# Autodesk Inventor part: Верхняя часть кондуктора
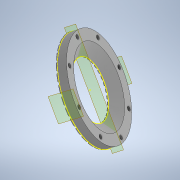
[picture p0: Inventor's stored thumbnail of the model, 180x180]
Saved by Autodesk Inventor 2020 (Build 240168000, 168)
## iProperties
Created: 2024-03
Part Number: Верхняя часть кондуктора
Material: Типовые
Document SubType Name: Modeling
Designer: User
Density: 1 g/cm^3
Appearance: Светло-серый
Author: User
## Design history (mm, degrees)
sketch "Эскиз1"
  geometry: C1 r 16 at (0, 0); C2 r 46 at (0, 0); 1 further point
  constraints: 2 centre point, 2 coincident
  dimensions: "d0" = 32 diameter of C1; "d1" = 92 diameter of C2
extrude "Выдавливание1" new body sketch "Эскиз1" distance "d2" = 2; taper "d3" = 0 deg
sketch "Эскиз2"
  geometry: C1 r 26 at (0, 0); C2 r 36 at (0, 0); C3 r 46 at (0, 0); 1 further point
  constraints: 3 centre point, 3 coincident
  dimensions: "d4" = 52 diameter of C1; "d14" = 92 diameter of C3
extrude "Выдавливание2" join sketch "Эскиз2" distance "d5" = 6.05; taper "d6" = 0 deg
sketch "Эскиз3"
  geometry: L1 (0, 46)-(0, 26); 3 further points
  constraints: 2 end point, 2 vertical alignment, 1 vertical, 2 other
node "РабПлоскость1"
sketch "Эскиз5"
  geometry: L1 (0, -46)-(0, 46) reference; L2 (0, 0)-(-1.5, 0); C1 r 1.5 at (-1.5, 0); 1 further point
  constraints: 2 end point, 1 centre point, 1 coincident, 1 horizontal, 1 midpoint
  dimensions: "d15" = 1.5 distance of L2.start L2.end; "d16" = 3 diameter of C1
extrude "Выдавливание4" cut sketch "Эскиз5" distance "d17" = 40; taper "d18" = 0 deg
sketch "Эскиз6"
  geometry: C1 r 16 at (0, 0); C2 r 46 at (0, 0); 1 further point
  constraints: 2 centre point, 2 coincident
extrude "Выдавливание5" join sketch "Эскиз6" distance "d22" = 8; taper "d23" = 0 deg
sketch "Эскиз7"
  geometry: L1 (-8.974, 45.116)-(-5.072, 25.5) reference; C1 r 1.5 at (-4.099, 41.618); A1 r 46 centre (0, 0) between (0, 46) and (-8.974, 45.116) reference; 1 further point
  constraints: 1 centre point
  dimensions: "d26" = 3 diameter of C1
extrude "Выдавливание6" cut sketch "Эскиз7" distance "d27" = 40; taper "d28" = 0 deg
sketch "Эскиз8"
  geometry: C1 r 26 at (0, 0); C2 r 46 at (0, 0); C3 r 1.5 at (-4.099, 41.618) reference; C4 r 1.5 at (-4.099, 41.618); 1 further point
  constraints: 3 centre point, 3 coincident
  dimensions: "d29" = 3 diameter of C4
extrude "Выдавливание7" join sketch "Эскиз8" distance "d30" = 8; taper "d31" = 0 deg
pattern_circular "Круговой массив3" dims angle "d33" = 360 deg
sketch "Эскиз9"
  geometry: C1 r 1.5 at (0, 0) reference; C2 r 1.5 at (0, 0); 1 further point
  constraints: 1 centre point, 1 coincident
  dimensions: "d35" = 3 diameter of C2
extrude "Выдавливание8" cut sketch "Эскиз9" distance "d36" = 20; taper "d37" = 0 deg
sketch "Эскиз10"
  geometry: C1 r 1.5 at (0, 0) reference; C2 r 1.5 at (0, 0); C3 r 1.5 at (-15.088, -28.228) reference; C4 r 1.5 at (-15.088, -28.228); C5 r 1.5 at (-45.718, -37.519) reference; C6 r 1.5 at (-45.718, -37.519); C7 r 1.5 at (-73.946, -22.431) reference; C8 r 1.5 at (-73.946, -22.431); C9 r 1.5 at (-83.237, 8.198) reference; C10 r 1.5 at (-83.237, 8.198); C11 r 1.5 at (-68.149, 36.426) reference; C12 r 1.5 at (-68.149, 36.426); 1 further point
  constraints: 6 centre point, 6 coincident
  dimensions: "d38" = 3 diameter of C2; "d39" = 3 diameter of C4; "d40" = 3 diameter of C6; "d41" = 3 diameter of C8; "d42" = 3 diameter of C10; "d43" = 3 diameter of C12
extrude "Выдавливание9" cut sketch "Эскиз10" distance "d44" = 20; taper "d45" = 0 deg
sketch "Эскиз11"
  geometry: L1 (60.933, 75.393)-(-60.762, 75.393); L2 (-60.762, 75.393)-(-60.762, -75.327); L3 (-60.762, -75.327)-(60.933, -75.327); L4 (60.933, -75.327)-(60.933, 75.393); 1 further point
  constraints: 8 end point, 2 parallel, 1 horizontal, 1 perpendicular
extrude "Выдавливание10" cut sketch "Эскиз11" distance "d46" = 15; taper "d47" = 0 deg
sketch "Эскиз12"
  geometry: C1 r 1.5 at (-26.53, -32.327) reference; C2 r 2 at (-26.53, -32.327); C3 r 1.5 at (-41.618, -4.099) reference; C4 r 2 at (-41.618, -4.099); C5 r 1.5 at (-32.327, 26.53) reference; C6 r 2 at (-32.327, 26.53); C7 r 1.5 at (-4.099, 41.618) reference; C8 r 2 at (-4.099, 41.618); C9 r 1.5 at (26.53, 32.327) reference; C10 r 2 at (26.53, 32.327); C11 r 1.5 at (41.618, 4.099) reference; C12 r 2 at (41.618, 4.099); C13 r 1.5 at (32.327, -26.53) reference; C14 r 2 at (32.327, -26.53); C15 r 1.5 at (4.099, -41.618) reference; C16 r 2 at (4.099, -41.618); 1 further point
  constraints: 8 centre point, 8 coincident
  dimensions: "d48" = 4 diameter of C2; "d49" = 4 diameter of C4; "d50" = 4 diameter of C6; "d51" = 4 diameter of C8; "d52" = 4 diameter of C10; "d53" = 4 diameter of C12; "d54" = 4 diameter of C14; "d55" = 4 diameter of C16
extrude "Выдавливание11" cut sketch "Эскиз12" distance "d56" = 15; taper "d57" = 0 deg
node "РабПлоскость3"
  node "РабПлоскость2"
sketch "Эскиз13"
  geometry: L1 (8, -26)-(0, -26) reference; L2 (8, -26)-(8, -36); L3 (8, -46)-(8, 46) reference; L4 (8, -36)-(0, -26); L5 (0, -26)-(8, -26); L6 (0, -25.556)-(0, -14.445) reference; L7 (8, 0)-(0, 0); 2 further points
  constraints: 8 end point, 2 point on line, 1 horizontal, 1 midpoint, 1 perpendicular
revolve "Вращение1" sketch "Эскиз13" stored, may be unused: angle "d59" = 90 deg
node "Твердое тело1"
pattern_circular "Круговой массив2" dims angle "d20" = 360 deg
other parameters: "d58" = -92
